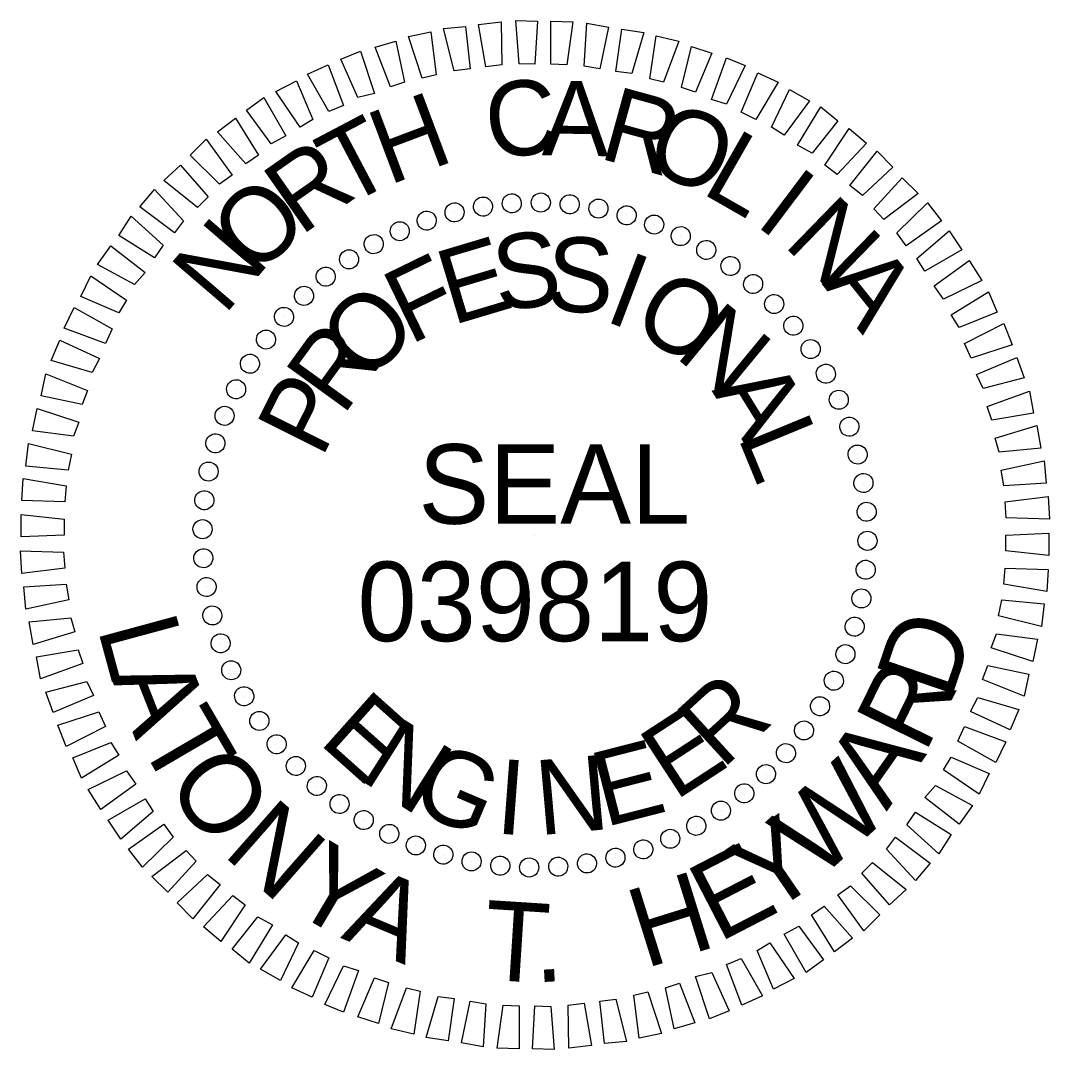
# Model space of a CAD drawing. Extents: x 2241081 to 2251104, y 658534 to 663427.
# Drawn here: x 2249618.9 to 2249696.5, y 661665.7 to 661743.3 of the extents above; entities that cross this region are included whole.
import ezdxf

# ---------------------------------------------------------------- set-up
doc = ezdxf.new("R2010")
doc.units = 0
doc.layers.add('Sheet Professional Seal CELL', color=7, linetype='Continuous')

msp = doc.modelspace()

# ---------------------------------------------------------------- linework, layer by layer
at = {"layer": 'Sheet Professional Seal CELL'}
for p, q in [((2249655.96, 661729.562), (2249655.96, 661729.562)), ((2249658.16, 661729.612), (2249658.16, 661729.612)), ((2249660.36, 661729.462), (2249660.36, 661729.462)), ((2249651.61, 661728.862), (2249651.61, 661728.862)), ((2249653.81, 661729.262), (2249653.81, 661729.262)), ((2249662.51, 661729.112), (2249662.51, 661729.112)), ((2249664.61, 661728.662), (2249664.61, 661728.662)), ((2249649.51, 661728.262), (2249649.51, 661728.262)), ((2249666.71, 661727.962), (2249666.71, 661727.962)), ((2249647.51, 661727.462), (2249647.51, 661727.462)), ((2249668.71, 661727.062), (2249668.71, 661727.062)), ((2249645.56, 661726.462), (2249645.56, 661726.462)), ((2249670.66, 661726.062), (2249670.66, 661726.062)), ((2249643.66, 661725.312), (2249643.66, 661725.312)), ((2249672.46, 661724.812), (2249672.46, 661724.812)), ((2249641.91, 661724.062), (2249641.91, 661724.062)), ((2249674.21, 661723.462), (2249674.21, 661723.462)), ((2249640.26, 661722.562), (2249640.26, 661722.562)), ((2249675.76, 661721.962), (2249675.76, 661721.962)), ((2249638.76, 661721.012), (2249638.76, 661721.012)), ((2249677.26, 661720.312), (2249677.26, 661720.312)), ((2249637.41, 661719.262), (2249637.41, 661719.262)), ((2249678.51, 661718.562), (2249678.51, 661718.562)), ((2249636.16, 661717.462), (2249636.16, 661717.462)), ((2249679.66, 661716.662), (2249679.66, 661716.662)), ((2249635.16, 661715.512), (2249635.16, 661715.512)), ((2249680.66, 661714.712), (2249680.66, 661714.712)), ((2249634.26, 661713.512), (2249634.26, 661713.512)), ((2249681.46, 661712.712), (2249681.46, 661712.712)), ((2249633.56, 661711.412), (2249633.56, 661711.412)), ((2249682.06, 661710.612), (2249682.06, 661710.612)), ((2249633.11, 661709.312), (2249633.11, 661709.312)), ((2249682.46, 661708.412), (2249682.46, 661708.412)), ((2249632.76, 661707.162), (2249632.76, 661707.162)), ((2249682.76, 661706.262), (2249682.76, 661706.262)), ((2249632.61, 661704.962), (2249632.61, 661704.962)), ((2249657.71, 661704.512), (2249657.71, 661704.512)), ((2249682.81, 661704.062), (2249682.81, 661704.062)), ((2249632.66, 661702.762), (2249632.66, 661702.762)), ((2249682.66, 661701.862), (2249682.66, 661701.862)), ((2249632.96, 661700.612), (2249632.96, 661700.612)), ((2249682.31, 661699.712), (2249682.31, 661699.712)), ((2249633.36, 661698.412), (2249633.36, 661698.412)), ((2249681.86, 661697.612), (2249681.86, 661697.612)), ((2249633.96, 661696.312), (2249633.96, 661696.312)), ((2249681.16, 661695.512), (2249681.16, 661695.512)), ((2249634.76, 661694.312), (2249634.76, 661694.312)), ((2249680.26, 661693.512), (2249680.26, 661693.512)), ((2249635.76, 661692.362), (2249635.76, 661692.362)), ((2249679.26, 661691.562), (2249679.26, 661691.562)), ((2249636.91, 661690.462), (2249636.91, 661690.462)), ((2249678.01, 661689.762), (2249678.01, 661689.762)), ((2249638.16, 661688.712), (2249638.16, 661688.712)), ((2249676.66, 661688.012), (2249676.66, 661688.012)), ((2249639.66, 661687.062), (2249639.66, 661687.062)), ((2249675.16, 661686.462), (2249675.16, 661686.462)), ((2249641.21, 661685.562), (2249641.21, 661685.562)), ((2249673.51, 661684.962), (2249673.51, 661684.962)), ((2249642.96, 661684.212), (2249642.96, 661684.212)), ((2249671.76, 661683.712), (2249671.76, 661683.712)), ((2249644.76, 661682.962), (2249644.76, 661682.962)), ((2249669.86, 661682.562), (2249669.86, 661682.562)), ((2249646.71, 661681.962), (2249646.71, 661681.962)), ((2249667.91, 661681.562), (2249667.91, 661681.562)), ((2249648.71, 661681.062), (2249648.71, 661681.062)), ((2249665.91, 661680.762), (2249665.91, 661680.762)), ((2249650.81, 661680.362), (2249650.81, 661680.362)), ((2249652.91, 661679.912), (2249652.91, 661679.912)), ((2249661.61, 661679.762), (2249661.61, 661679.762)), ((2249663.81, 661680.162), (2249663.81, 661680.162)), ((2249655.06, 661679.562), (2249655.06, 661679.562)), ((2249657.26, 661679.412), (2249657.26, 661679.412)), ((2249659.46, 661679.462), (2249659.46, 661679.462))]:
    msp.add_line(p, q, dxfattribs=at)
for points in [[(2249651.61, 661739.512), (2249650.81, 661742.712), (2249652.46, 661742.862), (2249652.81, 661739.662)], [(2249654.01, 661739.812), (2249653.46, 661743.012), (2249655.16, 661743.212), (2249655.21, 661739.962)], [(2249656.51, 661740.062), (2249656.26, 661743.312), (2249657.91, 661743.262), (2249657.71, 661740.012)], [(2249658.91, 661740.012), (2249658.91, 661743.262), (2249660.56, 661743.212), (2249660.11, 661739.962)], [(2249661.41, 661739.862), (2249661.61, 661743.112), (2249663.26, 661742.812), (2249662.61, 661739.662)], [(2249663.81, 661739.462), (2249664.26, 661742.662), (2249665.91, 661742.412), (2249665.01, 661739.312)], [(2249649.21, 661738.962), (2249648.16, 661742.112), (2249649.86, 661742.462), (2249650.26, 661739.212)], [(2249666.36, 661738.912), (2249666.86, 661742.162), (2249668.56, 661741.762), (2249667.41, 661738.662)], [(2249644.36, 661737.512), (2249643.06, 661740.412), (2249644.56, 661741.012), (2249645.61, 661737.812)], [(2249646.81, 661738.312), (2249645.66, 661741.312), (2249647.21, 661741.762), (2249647.86, 661738.662)], [(2249668.76, 661738.262), (2249669.51, 661741.362), (2249671.06, 661740.862), (2249669.81, 661737.912)], [(2249671.01, 661737.362), (2249672.16, 661740.512), (2249673.56, 661739.912), (2249672.16, 661737.012)], [(2249642.16, 661736.462), (2249640.56, 661739.262), (2249642.11, 661739.962), (2249643.26, 661736.912)], [(2249640.01, 661735.262), (2249638.16, 661737.962), (2249639.71, 661738.762), (2249640.96, 661735.862)], [(2249673.26, 661736.412), (2249674.51, 661739.362), (2249676.06, 661738.662), (2249674.36, 661735.862)], [(2249675.56, 661735.262), (2249676.91, 661738.112), (2249678.41, 661737.262), (2249676.51, 661734.662)], [(2249637.81, 661734.012), (2249635.96, 661736.562), (2249637.26, 661737.512), (2249638.91, 661734.612)], [(2249677.51, 661733.912), (2249679.26, 661736.812), (2249680.56, 661735.762), (2249678.61, 661733.312)], [(2249635.91, 661732.512), (2249633.76, 661734.912), (2249635.11, 661735.962), (2249636.86, 661733.162)], [(2249679.56, 661732.412), (2249681.41, 661735.162), (2249682.71, 661734.062), (2249680.51, 661731.712)], [(2249633.91, 661730.962), (2249631.71, 661733.162), (2249632.91, 661734.362), (2249634.86, 661731.662)], [(2249681.46, 661730.862), (2249683.51, 661733.462), (2249684.71, 661732.262), (2249682.41, 661730.112)], [(2249632.26, 661729.212), (2249629.71, 661731.262), (2249630.96, 661732.412), (2249633.06, 661730.012)], [(2249683.26, 661729.112), (2249685.41, 661731.462), (2249686.61, 661730.262), (2249684.01, 661728.312)], [(2249630.51, 661727.312), (2249627.91, 661729.262), (2249629.01, 661730.562), (2249631.21, 661728.212)], [(2249685.01, 661727.312), (2249687.31, 661729.562), (2249688.36, 661728.212), (2249685.71, 661726.312)], [(2249629.01, 661725.412), (2249626.31, 661727.112), (2249627.26, 661728.562), (2249629.66, 661726.362)], [(2249686.51, 661725.362), (2249688.96, 661727.462), (2249689.91, 661726.012), (2249687.11, 661724.412)], [(2249627.51, 661723.412), (2249624.71, 661724.912), (2249625.71, 661726.312), (2249628.31, 661724.312)], [(2249687.81, 661723.312), (2249690.46, 661725.212), (2249691.41, 661723.712), (2249688.51, 661722.312)], [(2249626.31, 661721.262), (2249623.46, 661722.512), (2249624.21, 661724.062), (2249626.91, 661722.212)], [(2249689.11, 661721.112), (2249691.91, 661722.862), (2249692.56, 661721.312), (2249689.71, 661720.162)], [(2249625.31, 661718.962), (2249622.21, 661720.112), (2249622.96, 661721.662), (2249625.81, 661720.062)], [(2249690.11, 661718.962), (2249693.06, 661720.462), (2249693.71, 661718.862), (2249690.61, 661717.862)], [(2249624.31, 661716.762), (2249621.21, 661717.662), (2249621.86, 661719.212), (2249624.86, 661717.812)], [(2249691.01, 661716.612), (2249694.06, 661717.912), (2249694.61, 661716.362), (2249691.51, 661715.562)], [(2249623.56, 661714.362), (2249620.46, 661715.012), (2249620.81, 661716.662), (2249623.96, 661715.412)], [(2249691.81, 661714.212), (2249695.01, 661715.362), (2249695.31, 661713.712), (2249692.16, 661713.162)], [(2249622.91, 661711.962), (2249619.81, 661712.362), (2249620.16, 661714.062), (2249623.31, 661713.012)], [(2249692.41, 661711.812), (2249695.56, 661712.762), (2249695.86, 661711.062), (2249692.71, 661710.762)], [(2249622.51, 661709.412), (2249619.31, 661709.712), (2249619.51, 661711.412), (2249622.76, 661710.612)], [(2249692.86, 661709.412), (2249696.11, 661710.112), (2249696.26, 661708.412), (2249693.06, 661708.212)], [(2249622.26, 661707.012), (2249619.01, 661707.112), (2249619.11, 661708.762), (2249622.36, 661708.212)], [(2249693.16, 661707.012), (2249696.41, 661707.412), (2249696.51, 661705.712), (2249693.26, 661705.812)], [(2249622.21, 661704.512), (2249618.96, 661704.362), (2249618.96, 661706.062), (2249622.21, 661705.712)], [(2249693.21, 661704.512), (2249696.46, 661704.662), (2249696.46, 661702.962), (2249693.21, 661703.312)], [(2249622.26, 661702.012), (2249619.01, 661701.612), (2249618.91, 661703.312), (2249622.16, 661703.212)], [(2249693.16, 661702.012), (2249696.41, 661701.912), (2249696.31, 661700.262), (2249693.06, 661700.812)], [(2249622.56, 661699.612), (2249619.31, 661698.912), (2249619.16, 661700.612), (2249622.36, 661700.812)], [(2249692.91, 661699.612), (2249696.11, 661699.312), (2249695.91, 661697.612), (2249692.66, 661698.412)], [(2249623.01, 661697.212), (2249619.86, 661696.262), (2249619.56, 661697.962), (2249622.71, 661698.262)], [(2249692.51, 661697.062), (2249695.61, 661696.662), (2249695.26, 661694.962), (2249692.11, 661696.012)], [(2249623.61, 661694.812), (2249620.41, 661693.662), (2249620.11, 661695.312), (2249623.26, 661695.862)], [(2249691.86, 661694.662), (2249694.96, 661694.012), (2249694.61, 661692.362), (2249691.46, 661693.612)], [(2249624.41, 661692.412), (2249621.36, 661691.112), (2249620.81, 661692.662), (2249623.91, 661693.462)], [(2249691.11, 661692.262), (2249694.21, 661691.362), (2249693.56, 661689.812), (2249690.56, 661691.212)], [(2249625.31, 661690.062), (2249622.36, 661688.562), (2249621.71, 661690.162), (2249624.81, 661691.162)], [(2249690.11, 661690.062), (2249693.21, 661688.912), (2249692.46, 661687.362), (2249689.61, 661688.962)], [(2249626.31, 661687.912), (2249623.51, 661686.162), (2249622.86, 661687.712), (2249625.71, 661688.862)], [(2249689.11, 661687.762), (2249691.96, 661686.512), (2249691.21, 661684.962), (2249688.51, 661686.812)], [(2249627.61, 661685.712), (2249624.96, 661683.812), (2249624.01, 661685.312), (2249626.91, 661686.712)], [(2249687.91, 661685.612), (2249690.71, 661684.112), (2249689.71, 661682.712), (2249687.11, 661684.712)], [(2249628.91, 661683.662), (2249626.46, 661681.562), (2249625.51, 661683.012), (2249628.31, 661684.612)], [(2249686.41, 661683.612), (2249689.11, 661681.912), (2249688.16, 661680.462), (2249685.76, 661682.662)], [(2249630.41, 661681.712), (2249628.11, 661679.462), (2249627.06, 661680.812), (2249629.71, 661682.712)], [(2249684.91, 661681.712), (2249687.51, 661679.762), (2249686.41, 661678.462), (2249684.21, 661680.812)], [(2249632.16, 661679.912), (2249630.01, 661677.562), (2249628.81, 661678.762), (2249631.41, 661680.712)], [(2249683.16, 661679.812), (2249685.71, 661677.762), (2249684.46, 661676.612), (2249682.36, 661679.012)], [(2249633.96, 661678.162), (2249631.91, 661675.562), (2249630.71, 661676.762), (2249633.01, 661678.912)], [(2249681.51, 661678.062), (2249683.71, 661675.862), (2249682.51, 661674.662), (2249680.56, 661677.362)], [(2249635.86, 661676.612), (2249634.01, 661673.862), (2249632.71, 661674.962), (2249634.91, 661677.312)], [(2249679.51, 661676.512), (2249681.66, 661674.112), (2249680.31, 661673.062), (2249678.56, 661675.862)], [(2249637.91, 661675.112), (2249636.16, 661672.212), (2249634.86, 661673.262), (2249636.81, 661675.712)], [(2249639.86, 661673.762), (2249638.51, 661670.912), (2249637.01, 661671.762), (2249638.91, 661674.362)], [(2249677.61, 661675.012), (2249679.46, 661672.462), (2249678.16, 661671.512), (2249676.51, 661674.412)], [(2249675.41, 661673.762), (2249677.26, 661671.062), (2249675.71, 661670.262), (2249674.46, 661673.162)], [(2249642.16, 661672.612), (2249640.91, 661669.662), (2249639.36, 661670.362), (2249641.06, 661673.162)], [(2249644.41, 661671.662), (2249643.26, 661668.512), (2249641.86, 661669.112), (2249643.26, 661672.012)], [(2249673.26, 661672.562), (2249674.86, 661669.762), (2249673.31, 661669.062), (2249672.16, 661672.112)], [(2249671.06, 661671.512), (2249672.36, 661668.612), (2249670.86, 661668.012), (2249669.81, 661671.212)], [(2249646.66, 661670.762), (2249645.91, 661667.662), (2249644.36, 661668.162), (2249645.61, 661671.112)], [(2249668.61, 661670.712), (2249669.76, 661667.712), (2249668.21, 661667.262), (2249667.56, 661670.362)], [(2249649.06, 661670.112), (2249648.56, 661666.862), (2249646.86, 661667.262), (2249648.01, 661670.362)], [(2249651.61, 661669.562), (2249651.16, 661666.362), (2249649.51, 661666.612), (2249650.41, 661669.712)], [(2249666.21, 661670.062), (2249667.26, 661666.912), (2249665.56, 661666.562), (2249665.16, 661669.812)], [(2249654.01, 661669.162), (2249653.81, 661665.912), (2249652.16, 661666.212), (2249652.81, 661669.362)], [(2249656.51, 661669.012), (2249656.51, 661665.762), (2249654.86, 661665.812), (2249655.31, 661669.062)], [(2249658.91, 661668.962), (2249659.16, 661665.712), (2249657.51, 661665.762), (2249657.71, 661669.012)], [(2249661.41, 661669.212), (2249661.96, 661666.012), (2249660.26, 661665.812), (2249660.21, 661669.062)], [(2249663.81, 661669.512), (2249664.61, 661666.312), (2249662.96, 661666.162), (2249662.61, 661669.362)]]:
    msp.add_lwpolyline(points, close=True, dxfattribs=at)
for centre, major_axis in [((2249655.961, 661729.531), (-0.05, 0.718)), ((2249658.148, 661729.588), (0.013, 0.72)), ((2249660.332, 661729.455), (0.075, 0.716)), ((2249651.643, 661728.847), (-0.174, 0.699)), ((2249653.787, 661729.283), (-0.113, 0.711)), ((2249662.496, 661729.131), (0.137, 0.707)), ((2249664.623, 661728.621), (0.198, 0.692)), ((2249649.545, 661728.226), (-0.234, 0.681)), ((2249666.698, 661727.926), (0.258, 0.672)), ((2249647.509, 661727.424), (-0.293, 0.658)), ((2249668.704, 661727.054), (0.316, 0.647)), ((2249645.551, 661726.448), (-0.349, 0.63)), ((2249670.627, 661726.01), (0.371, 0.617)), ((2249643.686, 661725.304), (-0.403, 0.597)), ((2249672.452, 661724.802), (0.423, 0.582)), ((2249641.927, 661724.003), (-0.453, 0.56)), ((2249674.164, 661723.44), (0.472, 0.543)), ((2249640.288, 661722.553), (-0.5, 0.518)), ((2249675.751, 661721.934), (0.518, 0.5)), ((2249638.782, 661720.966), (-0.543, 0.472)), ((2249677.201, 661720.295), (0.56, 0.453)), ((2249637.42, 661719.254), (-0.582, 0.423)), ((2249678.502, 661718.537), (0.597, 0.403)), ((2249636.212, 661717.429), (-0.617, 0.371)), ((2249679.646, 661716.671), (0.63, 0.349)), ((2249635.168, 661715.506), (-0.647, 0.316)), ((2249680.622, 661714.713), (0.658, 0.293)), ((2249634.296, 661713.5), (-0.672, 0.258)), ((2249681.424, 661712.677), (0.681, 0.234)), ((2249633.602, 661711.425), (-0.692, 0.198)), ((2249682.045, 661710.579), (0.699, 0.174)), ((2249633.091, 661709.298), (-0.707, 0.137)), ((2249682.481, 661708.435), (0.711, 0.113)), ((2249632.768, 661707.134), (-0.716, 0.075)), ((2249682.729, 661706.262), (0.718, 0.05)), ((2249632.634, 661704.95), (-0.72, 0.013)), ((2249682.786, 661704.074), (0.72, -0.013)), ((2249632.691, 661702.763), (-0.718, -0.05)), ((2249682.653, 661701.89), (0.716, -0.075)), ((2249632.939, 661700.589), (-0.711, -0.113)), ((2249682.329, 661699.727), (0.707, -0.137)), ((2249633.375, 661698.445), (-0.699, -0.174)), ((2249681.819, 661697.599), (0.692, -0.198)), ((2249633.997, 661696.347), (-0.681, -0.234)), ((2249681.124, 661695.524), (0.672, -0.258)), ((2249634.798, 661694.311), (-0.658, -0.293)), ((2249680.252, 661693.518), (0.647, -0.316)), ((2249635.775, 661692.353), (-0.63, -0.349)), ((2249679.208, 661691.595), (0.617, -0.371)), ((2249636.918, 661690.488), (-0.597, -0.403)), ((2249678, 661689.77), (0.582, -0.423)), ((2249638.219, 661688.729), (-0.56, -0.453)), ((2249676.638, 661688.058), (0.543, -0.472)), ((2249639.669, 661687.09), (-0.518, -0.5)), ((2249675.132, 661686.471), (0.5, -0.518)), ((2249641.256, 661685.584), (-0.472, -0.543)), ((2249673.493, 661685.021), (0.453, -0.56)), ((2249642.968, 661684.222), (-0.423, -0.582)), ((2249671.735, 661683.72), (0.403, -0.597)), ((2249644.793, 661683.014), (-0.371, -0.617)), ((2249669.869, 661682.577), (0.349, -0.63)), ((2249646.716, 661681.97), (-0.316, -0.647)), ((2249667.911, 661681.6), (0.293, -0.658)), ((2249648.722, 661681.098), (-0.258, -0.672)), ((2249665.875, 661680.798), (0.234, -0.681)), ((2249650.797, 661680.404), (-0.198, -0.692)), ((2249652.925, 661679.893), (-0.137, -0.707)), ((2249661.633, 661679.741), (0.113, -0.711)), ((2249663.777, 661680.177), (0.174, -0.699)), ((2249655.089, 661679.569), (-0.075, -0.716)), ((2249657.272, 661679.436), (-0.013, -0.72)), ((2249659.46, 661679.493), (0.05, -0.718))]:
    msp.add_ellipse(centre, major_axis=major_axis, ratio=0.999708, dxfattribs=at)

# ---------------------------------------------------------------- texts
for s, height, rotation, p in [('C', 5.638, 6.2198, (2249654.26, 661732.862)), ('A', 5.638, 359.02025, (2249658.21, 661733.162)), ('R', 5.638, 344.62103, (2249662.41, 661732.962)), ('H', 5.638, 20.61941, (2249646.66, 661730.862)), ('O', 5.638, 337.4211, (2249665.76, 661732.212)), ('T', 5.638, 27.81971, (2249643.41, 661729.212)), ('L', 5.638, 330.22081, (2249670.16, 661730.362)), ('R', 5.639, 35.02044, (2249640.01, 661727.012)), ('I', 5.638, 323.02008, (2249674.21, 661727.962)), ('O', 5.639, 42.22168, (2249636.56, 661723.912)), ('N', 5.639, 315.81884, (2249676.36, 661726.412)), ('N', 5.639, 49.42343, (2249634.26, 661721.012)), ('S', 5.638, 7.25554, (2249654.91, 661721.362)), ('S', 5.638, 357.90033, (2249658.51, 661721.412)), ('E', 5.638, 16.611, (2249651.46, 661720.312)), ('F', 5.638, 25.96697, (2249648.26, 661718.812)), ('I', 5.638, 339.18954, (2249662.81, 661720.712)), ('A', 5.639, 308.61709, (2249679.31, 661723.462)), ('O', 5.638, 329.83342, (2249664.81, 661720.012)), ('O', 5.639, 44.68117, (2249644.96, 661715.862)), ('N', 5.639, 320.47655, (2249668.16, 661718.012)), ('R', 5.639, 54.03958, (2249643.21, 661713.412)), ('P', 5.639, 63.39882, (2249641.61, 661710.212)), ('A', 5.639, 301.7602, (2249671.01, 661715.412)), ('L', 5.639, 292.40078, (2249672.96, 661711.962)), ('SEAL', 5.9982, 359.99993, (2249648.911, 661705.361)), ('039819', 5.9982, 359.99993, (2249644.321, 661696.504)), ('L', 5.998, 285.17415, (2249624.702, 661697.472)), ('D', 5.998, 71.22469, (2249689.023, 661691.918)), ('R', 5.998, 63.74443, (2249687.117, 661687.949)), ('A', 5.998, 291.44891, (2249625.669, 661693.906)), ('R', 5.639, 42.48134, (2249671.81, 661686.762)), ('E', 5.638, 318.27682, (2249641.31, 661688.862)), ('T', 5.998, 300.28922, (2249627.679, 661689.108)), ('E', 5.638, 33.12402, (2249668.26, 661684.412)), ('N', 5.639, 327.63389, (2249644.31, 661686.162)), ('E', 5.638, 14.4117, (2249662.96, 661682.462)), ('A', 5.998, 54.90412, (2249684.223, 661683.626)), ('G', 5.638, 336.99017, (2249648.11, 661683.912)), ('O', 5.998, 307.08945, (2249629.715, 661685.661)), ('I', 5.638, 355.70113, (2249654.66, 661682.012)), ('N', 5.638, 5.05632, (2249658.01, 661681.862)), ('W', 5.998, 42.37005, (2249679.058, 661678.37)), ('N', 5.998, 318.64986, (2249634.06, 661680.433)), ('Y', 5.998, 34.45704, (2249675.256, 661675.68)), ('Y', 5.998, 329.37569, (2249638.955, 661676.452)), ('E', 5.998, 27.34771, (2249671.553, 661673.73)), ('H', 5.998, 17.36372, (2249666.006, 661671.797)), ('A', 5.998, 337.28869, (2249642.996, 661674.137)), ('T', 5.998, 356.32935, (2249653.711, 661670.999)), ('.', 5.998, 3.12959, (2249657.707, 661670.761))]:
    msp.add_text(s, height=height, rotation=rotation, dxfattribs=at).set_placement(p)

doc.saveas('drawing.dxf')
